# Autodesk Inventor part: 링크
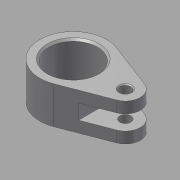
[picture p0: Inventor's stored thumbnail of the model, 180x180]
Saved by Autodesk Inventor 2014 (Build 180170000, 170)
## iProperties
Created: 2015-12
Part Number: 링크
Material: 강철, 연강
Document SubType Name: Modeling
Designer: mduedu
Density: 7.86 g/cm^3
Appearance: Steel
Author: mduedu
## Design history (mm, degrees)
sketch "스케치1"
  geometry: L1 (6.429, -16.813)-(30.857, -7.472); L2 (6.429, 16.813)-(30.857, 7.472); A1 r 18 centre (0, 0) between (6.429, 16.813) and (6.429, -16.813); A2 r 8 centre (28, 0) between (30.857, -7.472) and (30.857, 7.472); 1 further point
  constraints: 4 end point, 4 point on circle, 4 tangent, 2 centre point, 1 coincident, 1 horizontal alignment
  dimensions: "d0" = 18 radius of A1; "d1" = 8 radius of A2; "d2" = 28 distance of A2.centre point (0, 0)
extrude "돌출1" new body sketch "스케치1" stored distance "d3" = 20; taper "d4" = 0 deg
sketch "스케치2"
  geometry: L1 (6.429, 16.813)-(30.857, 7.472) reference; L2 (30.857, -7.472)-(6.429, -16.813) reference; L3 (16, 13.153)-(16, -13.153); A1 r 8 centre (28, 0) between (30.857, -7.472) and (30.857, 7.472) reference; 1 further point
  constraints: 2 end point, 2 point on line, 1 vertical
  dimensions: "d5" = 20 dimension on A1 L3
extrude "돌출2" cut sketch "스케치2" stored distance "d6" = 8; taper "d7" = 0 deg
hole "구멍1" diameter "d10" = 26; stored, may be unused: countersink angle "d14" = 90 deg, drill point angle "d16" = 118 deg; dims "d8" = 10, "d9" = 10, "d11" = 6, "d12" = 4, "d13" = 2, "d15" = 8
hole "구멍2" diameter "d19" = 6; stored, may be unused: countersink angle "d23" = 90 deg, drill point angle "d25" = 118 deg; dims "d20" = 6, "d21" = 4, "d22" = 2, "d24" = 8, "d32" = 10, "d33" = 10
chamfer "모따기1" distance "d26" = 1; stored, may be unused: second distance "d27" = 2, angle "d28" = 45 deg
chamfer "모따기2" distance "d29" = 0.5; stored, may be unused: second distance "d30" = 2, angle "d31" = 45 deg
node "솔리드1"
